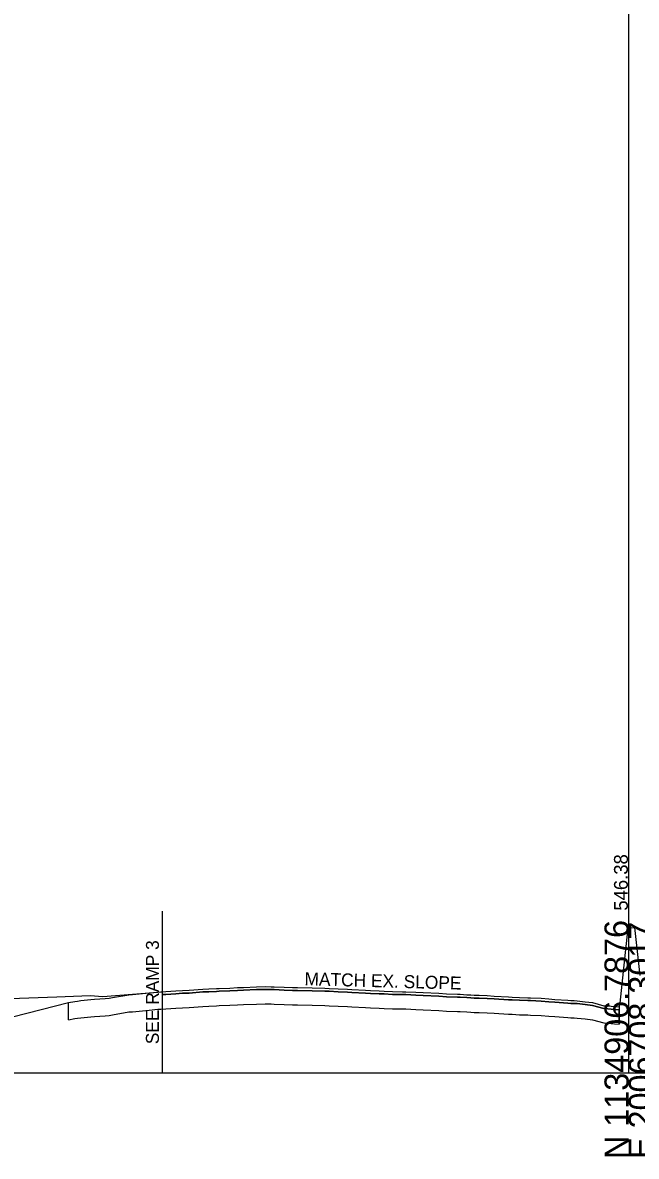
# Model space of a CAD drawing. Extents: x -201 to 2007062, y -213 to 1139737.
# Drawn here: x 1179.9 to 1250.9, y 990.3 to 1121.7 of the extents above; entities that cross this region are included whole.
import ezdxf

# ---------------------------------------------------------------- set-up
doc = ezdxf.new("R2010")
doc.units = 0
for name, color, linetype in [('RD_DTM_Design_FG', 7, 'Continuous'), ('RD_GPK_XS_Cell', 7, 'Continuous'), ('RD_XS_ExGround', 7, 'Continuous'), ('RD_XS_ExPaveRet', 7, 'Continuous'), ('RD_XS_PaveOvlay', 7, 'Continuous'), ('RD_XS_SideStreet', 7, 'Continuous'), ('RD_XS_TX_Elev_EX', 7, 'Continuous'), ('RD_XS_TX_Slope', 7, 'Continuous')]:
    doc.layers.add(name, color=color, linetype=linetype)

msp = doc.modelspace()

# ---------------------------------------------------------------- linework, layer by layer
at = {"layer": 'RD_DTM_Design_FG'}
msp.add_lwpolyline([(1069.88, 1075.08), (1095.05, 1049.89), (1143.64, 1001.26), (1148.38, 1002.83), (1161.65, 1007.23), (1162.29, 1007.33), (1165.65, 1007.87), (1166.43, 1007.93), (1171.66, 1008.34), (1172.95, 1008.39), (1183.82, 1008.8), (1187.67, 1008.95), (1189.12, 1008.83), (1196, 1009.37)], dxfattribs=at)
at = {"layer": 'RD_GPK_XS_Cell'}
for p, q in [((1250, 1000), (1250, 1250.21)), ((1000, 1000), (1250, 1000)), ((1250, 1000), (1500, 1000))]:
    msp.add_line(p, q, dxfattribs=at)
at = {"layer": 'RD_XS_ExGround'}
msp.add_lwpolyline([(1177.12, 1006.09), (1185.14, 1008.13), (1185.88, 1008.26), (1186.18, 1008.3), (1186.6, 1008.35), (1187.74, 1008.47), (1188.17, 1008.5), (1189.4, 1008.6), (1189.86, 1008.64), (1190.25, 1008.71), (1192.14, 1009.03), (1192.57, 1009.06), (1194.1, 1009.2), (1194.49, 1009.24), (1195.48, 1009.34), (1195.86, 1009.36), (1196.41, 1009.39), (1197.57, 1009.48), (1198.34, 1009.53), (1199.14, 1009.57), (1200.71, 1009.68), (1201.39, 1009.71), (1202.27, 1009.75), (1202.59, 1009.77), (1203.84, 1009.81), (1204.71, 1009.85), (1205.41, 1009.88), (1206.91, 1009.95), (1207.94, 1009.97), (1208.61, 1009.96), (1208.95, 1009.95), (1210.11, 1009.89), (1211.07, 1009.87), (1211.68, 1009.87), (1213.38, 1009.84), (1214.81, 1009.79), (1215.32, 1009.76), (1216.38, 1009.71), (1217.44, 1009.66), (1217.94, 1009.63), (1219.55, 1009.56), (1220.11, 1009.51), (1221.1, 1009.48), (1221.68, 1009.45), (1222.65, 1009.4), (1223.8, 1009.38), (1224.21, 1009.38), (1225.38, 1009.32), (1226.22, 1009.27), (1228.04, 1009.21), (1228.91, 1009.14), (1230.17, 1009.1), (1230.48, 1009.09), (1231.25, 1009.03), (1231.74, 1009.01), (1232.13, 1008.97), (1232.71, 1008.97), (1233.62, 1008.93), (1234.41, 1008.88), (1236.07, 1008.78), (1236.53, 1008.76), (1237.37, 1008.72), (1238.32, 1008.69), (1238.65, 1008.68), (1239.88, 1008.63), (1240.77, 1008.55), (1241.45, 1008.49), (1242.97, 1008.39), (1243.32, 1008.36), (1243.67, 1008.35), (1244.02, 1008.33), (1244.95, 1008.22), (1245.8, 1008.12), (1247.14, 1007.76), (1247.58, 1007.73), (1248.35, 1007.66), (1248.91, 1007.62), (1249.01, 1008.05), (1249.64, 1013.92), (1249.94, 1016.76), (1250.66, 1016.82), (1251.28, 1011.26)], dxfattribs=at)
at = {"layer": 'RD_XS_ExPaveRet'}
for p, q in [((1196, 1009.04), (1196, 1007.37)), ((1185.14, 1006.13), (1185.14, 1008.13)), ((1196.41, 1007.39), (1197.57, 1007.48)), ((1196.41, 1007.39), (1197.57, 1007.48)), ((1197.57, 1007.48), (1198.34, 1007.53)), ((1197.57, 1007.48), (1198.34, 1007.53)), ((1198.34, 1007.53), (1199.14, 1007.57)), ((1198.34, 1007.53), (1199.14, 1007.57)), ((1199.14, 1007.57), (1200.71, 1007.68)), ((1199.14, 1007.57), (1200.71, 1007.68)), ((1200.71, 1007.68), (1201.39, 1007.71)), ((1200.71, 1007.68), (1201.39, 1007.71)), ((1201.39, 1007.71), (1202.27, 1007.75)), ((1201.39, 1007.71), (1202.27, 1007.75)), ((1202.27, 1007.75), (1202.59, 1007.77)), ((1202.27, 1007.75), (1202.59, 1007.77)), ((1202.59, 1007.77), (1203.84, 1007.81)), ((1202.59, 1007.77), (1203.84, 1007.81)), ((1203.84, 1007.81), (1204.71, 1007.85)), ((1203.84, 1007.81), (1204.71, 1007.85)), ((1204.71, 1007.85), (1205.41, 1007.88)), ((1204.71, 1007.85), (1205.41, 1007.88)), ((1205.41, 1007.88), (1206.91, 1007.95)), ((1205.41, 1007.88), (1206.91, 1007.95)), ((1206.91, 1007.95), (1207.94, 1007.97)), ((1206.91, 1007.95), (1207.94, 1007.97)), ((1207.94, 1007.97), (1208.61, 1007.96)), ((1207.94, 1007.97), (1208.61, 1007.96)), ((1208.61, 1007.96), (1208.95, 1007.95)), ((1208.61, 1007.96), (1208.95, 1007.95)), ((1208.95, 1007.95), (1210.11, 1007.89)), ((1208.95, 1007.95), (1210.11, 1007.89)), ((1210.11, 1007.89), (1211.07, 1007.87)), ((1210.11, 1007.89), (1211.07, 1007.87)), ((1211.07, 1007.87), (1211.68, 1007.87)), ((1211.07, 1007.87), (1211.68, 1007.87)), ((1211.68, 1007.87), (1213.38, 1007.84)), ((1211.68, 1007.87), (1213.38, 1007.84)), ((1213.38, 1007.84), (1214.81, 1007.79)), ((1213.38, 1007.84), (1214.81, 1007.79)), ((1214.81, 1007.79), (1215.32, 1007.76)), ((1214.81, 1007.79), (1215.32, 1007.76)), ((1215.32, 1007.76), (1216.38, 1007.71)), ((1215.32, 1007.76), (1216.38, 1007.71)), ((1216.38, 1007.71), (1217.44, 1007.66)), ((1216.38, 1007.71), (1217.44, 1007.66)), ((1217.44, 1007.66), (1217.94, 1007.63)), ((1217.44, 1007.66), (1217.94, 1007.63)), ((1217.94, 1007.63), (1219.55, 1007.56)), ((1217.94, 1007.63), (1219.55, 1007.56)), ((1219.55, 1007.56), (1220.11, 1007.51)), ((1219.55, 1007.56), (1220.11, 1007.51)), ((1220.11, 1007.51), (1221.1, 1007.48)), ((1220.11, 1007.51), (1221.1, 1007.48)), ((1221.1, 1007.48), (1221.68, 1007.45)), ((1221.1, 1007.48), (1221.68, 1007.45)), ((1248.91, 1007.62), (1248.91, 1005.62)), ((1185.14, 1006.13), (1185.88, 1006.26)), ((1185.88, 1006.26), (1186.18, 1006.3)), ((1186.18, 1006.3), (1186.6, 1006.35)), ((1186.6, 1006.35), (1187.74, 1006.47)), ((1187.74, 1006.47), (1188.17, 1006.5)), ((1188.17, 1006.5), (1189.4, 1006.6)), ((1189.4, 1006.6), (1189.86, 1006.64)), ((1189.86, 1006.64), (1190.25, 1006.71)), ((1190.25, 1006.71), (1192.14, 1007.03)), ((1192.14, 1007.03), (1192.57, 1007.06)), ((1192.57, 1007.06), (1194.1, 1007.2)), ((1194.1, 1007.2), (1194.49, 1007.24)), ((1194.49, 1007.24), (1195.48, 1007.34)), ((1195.48, 1007.34), (1195.86, 1007.36)), ((1195.86, 1007.36), (1196.41, 1007.39)), ((1196, 1007.37), (1196.41, 1007.39)), ((1221.68, 1007.45), (1222.65, 1007.4)), ((1221.68, 1007.45), (1222.65, 1007.4)), ((1222.65, 1007.4), (1223.8, 1007.38)), ((1222.65, 1007.4), (1223.8, 1007.38)), ((1223.8, 1007.38), (1224.21, 1007.38)), ((1223.8, 1007.38), (1224.21, 1007.38)), ((1224.21, 1007.38), (1225.38, 1007.32)), ((1224.21, 1007.38), (1225.38, 1007.32)), ((1225.38, 1007.32), (1226.22, 1007.27)), ((1225.38, 1007.32), (1226.22, 1007.27)), ((1226.22, 1007.27), (1228.04, 1007.21)), ((1226.22, 1007.27), (1228.04, 1007.21)), ((1228.04, 1007.21), (1228.91, 1007.14)), ((1228.04, 1007.21), (1228.91, 1007.14)), ((1228.91, 1007.14), (1230.17, 1007.1)), ((1228.91, 1007.14), (1230.17, 1007.1)), ((1230.17, 1007.1), (1230.48, 1007.09)), ((1230.17, 1007.1), (1230.48, 1007.09)), ((1230.48, 1007.09), (1231.25, 1007.03)), ((1230.48, 1007.09), (1231.25, 1007.03)), ((1231.25, 1007.03), (1231.74, 1007.01)), ((1231.25, 1007.03), (1231.74, 1007.01)), ((1231.74, 1007.01), (1232.13, 1006.97)), ((1231.74, 1007.01), (1232.13, 1006.97)), ((1232.13, 1006.97), (1232.71, 1006.97)), ((1232.13, 1006.97), (1232.71, 1006.97)), ((1232.71, 1006.97), (1233.62, 1006.93)), ((1232.71, 1006.97), (1233.62, 1006.93)), ((1233.62, 1006.93), (1234.41, 1006.88)), ((1233.62, 1006.93), (1234.41, 1006.88)), ((1234.41, 1006.88), (1236.07, 1006.78)), ((1234.41, 1006.88), (1236.07, 1006.78)), ((1236.07, 1006.78), (1236.53, 1006.76)), ((1236.07, 1006.78), (1236.53, 1006.76)), ((1236.53, 1006.76), (1237.37, 1006.72)), ((1236.53, 1006.76), (1237.37, 1006.72)), ((1237.37, 1006.72), (1238.32, 1006.69)), ((1237.37, 1006.72), (1238.32, 1006.69)), ((1238.32, 1006.69), (1238.65, 1006.68)), ((1238.32, 1006.69), (1238.65, 1006.68)), ((1238.65, 1006.68), (1239.88, 1006.63)), ((1238.65, 1006.68), (1239.88, 1006.63)), ((1239.88, 1006.63), (1240.77, 1006.55)), ((1239.88, 1006.63), (1240.77, 1006.55)), ((1240.77, 1006.55), (1241.45, 1006.49)), ((1240.77, 1006.55), (1241.45, 1006.49)), ((1241.45, 1006.49), (1242.97, 1006.39)), ((1241.45, 1006.49), (1242.97, 1006.39)), ((1242.97, 1006.39), (1243.32, 1006.36)), ((1242.97, 1006.39), (1243.32, 1006.36)), ((1243.32, 1006.36), (1243.67, 1006.35)), ((1243.32, 1006.36), (1243.67, 1006.35)), ((1243.67, 1006.35), (1244.02, 1006.33)), ((1243.67, 1006.35), (1244.02, 1006.33)), ((1244.02, 1006.33), (1244.95, 1006.22)), ((1244.02, 1006.33), (1244.95, 1006.22)), ((1244.95, 1006.22), (1245.8, 1006.12)), ((1244.95, 1006.22), (1245.8, 1006.12)), ((1248.91, 1005.62), (1248.91, 1007.29)), ((1245.8, 1006.12), (1247.14, 1005.76)), ((1245.8, 1006.12), (1247.14, 1005.76)), ((1247.14, 1005.76), (1247.58, 1005.73)), ((1247.14, 1005.76), (1247.58, 1005.73)), ((1247.58, 1005.73), (1248.35, 1005.66)), ((1247.58, 1005.73), (1248.35, 1005.66)), ((1248.35, 1005.66), (1248.91, 1005.62)), ((1248.35, 1005.66), (1248.91, 1005.62))]:
    msp.add_line(p, q, dxfattribs=at)
msp.add_lwpolyline([(1248.91, 1007.29), (1248.35, 1007.33), (1247.58, 1007.4), (1247.14, 1007.42), (1245.8, 1007.79), (1244.95, 1007.89), (1244.02, 1008), (1243.67, 1008.02), (1243.32, 1008.03), (1242.97, 1008.05), (1241.45, 1008.15), (1240.77, 1008.22), (1239.88, 1008.3), (1238.65, 1008.35), (1238.32, 1008.36), (1237.37, 1008.39), (1236.53, 1008.43), (1236.07, 1008.45), (1234.41, 1008.55), (1233.62, 1008.59), (1232.71, 1008.63), (1232.13, 1008.64), (1231.74, 1008.68), (1231.25, 1008.7), (1230.48, 1008.75), (1230.17, 1008.76), (1228.91, 1008.8), (1228.04, 1008.88), (1226.22, 1008.94), (1225.38, 1008.98), (1224.21, 1009.04), (1223.8, 1009.04), (1222.65, 1009.07), (1221.68, 1009.12), (1221.1, 1009.15), (1220.11, 1009.18), (1219.55, 1009.22), (1217.94, 1009.3), (1217.44, 1009.33), (1216.38, 1009.38), (1215.32, 1009.43), (1214.81, 1009.46), (1213.38, 1009.5), (1211.68, 1009.54), (1211.07, 1009.54), (1210.11, 1009.56), (1208.95, 1009.62), (1208.61, 1009.63), (1207.94, 1009.63), (1206.91, 1009.62), (1205.41, 1009.55), (1204.71, 1009.51), (1203.84, 1009.48), (1202.59, 1009.44), (1202.27, 1009.42), (1201.39, 1009.38), (1200.71, 1009.35), (1199.14, 1009.23), (1198.34, 1009.2), (1197.57, 1009.15), (1196.41, 1009.06), (1196, 1009.04)], dxfattribs=at)
at = {"layer": 'RD_XS_PaveOvlay'}
msp.add_line((1196, 1009.37), (1196, 1009.04), dxfattribs=at)
for points in [[(1196, 1009.37), (1196.41, 1009.39), (1197.57, 1009.48), (1198.34, 1009.53), (1199.14, 1009.57), (1200.71, 1009.68), (1201.39, 1009.71), (1202.27, 1009.75), (1202.59, 1009.77), (1203.84, 1009.81), (1204.71, 1009.85), (1205.41, 1009.88), (1206.91, 1009.95), (1207.94, 1009.97), (1208.61, 1009.96), (1208.95, 1009.95), (1210.11, 1009.89), (1211.07, 1009.87), (1211.68, 1009.87), (1213.38, 1009.84), (1214.81, 1009.79), (1215.32, 1009.76), (1216.38, 1009.71), (1217.44, 1009.66), (1217.94, 1009.63), (1219.55, 1009.56), (1220.11, 1009.51), (1221.1, 1009.48), (1221.68, 1009.45), (1222.65, 1009.4), (1223.8, 1009.38), (1224.21, 1009.38), (1225.38, 1009.32), (1226.22, 1009.27), (1228.04, 1009.21), (1228.91, 1009.14), (1230.17, 1009.1), (1230.48, 1009.09), (1231.25, 1009.03), (1231.74, 1009.01), (1232.13, 1008.97), (1232.71, 1008.97), (1233.62, 1008.93), (1234.41, 1008.88), (1236.07, 1008.78), (1236.53, 1008.76), (1237.37, 1008.72), (1238.32, 1008.69), (1238.65, 1008.68), (1239.88, 1008.63), (1240.77, 1008.55), (1241.45, 1008.49), (1242.97, 1008.39), (1243.32, 1008.36), (1243.67, 1008.35), (1244.02, 1008.33), (1244.95, 1008.22), (1245.8, 1008.12), (1247.14, 1007.76), (1247.58, 1007.73), (1248.35, 1007.66), (1248.91, 1007.62), (1248.91, 1007.62)], [(1196, 1009.04), (1196.41, 1009.06), (1197.57, 1009.15), (1198.34, 1009.2), (1199.14, 1009.23), (1200.71, 1009.35), (1201.39, 1009.38), (1202.27, 1009.42), (1202.59, 1009.44), (1203.84, 1009.48), (1204.71, 1009.51), (1205.41, 1009.55), (1206.91, 1009.62), (1207.94, 1009.63), (1208.61, 1009.63), (1208.95, 1009.62), (1210.11, 1009.56), (1211.07, 1009.54), (1211.68, 1009.54), (1213.38, 1009.5), (1214.81, 1009.46), (1215.32, 1009.43), (1216.38, 1009.38), (1217.44, 1009.33), (1217.94, 1009.3), (1219.55, 1009.22), (1220.11, 1009.18), (1221.1, 1009.15), (1221.68, 1009.12), (1222.65, 1009.07), (1223.8, 1009.04), (1224.21, 1009.04), (1225.38, 1008.98), (1226.22, 1008.94), (1228.04, 1008.88), (1228.91, 1008.8), (1230.17, 1008.76), (1230.48, 1008.75), (1231.25, 1008.7), (1231.74, 1008.68), (1232.13, 1008.64), (1232.71, 1008.63), (1233.62, 1008.59), (1234.41, 1008.55), (1236.07, 1008.45), (1236.53, 1008.43), (1237.37, 1008.39), (1238.32, 1008.36), (1238.65, 1008.35), (1239.88, 1008.3), (1240.77, 1008.22), (1241.45, 1008.15), (1242.97, 1008.05), (1243.32, 1008.03), (1243.67, 1008.02), (1244.02, 1008), (1244.95, 1007.89), (1245.8, 1007.79), (1247.14, 1007.42), (1247.58, 1007.4), (1248.35, 1007.33), (1248.91, 1007.29), (1248.91, 1007.29)]]:
    msp.add_lwpolyline(points, dxfattribs=at)
at = {"layer": 'RD_XS_SideStreet'}
msp.add_line((1196, 1018.71), (1196, 1000.03), dxfattribs=at)

# ---------------------------------------------------------------- texts
at = {"layer": 'RD_GPK_XS_Cell'}
for s, p in [('N 1134906.7876', (1250, 990)), ('E 2006708.3017', (1252.8, 990))]:
    msp.add_text(s, height=2.8, rotation=90, dxfattribs=at).set_placement(p)
at = {"layer": 'RD_XS_SideStreet'}
msp.add_text('SEE RAMP 3', height=1.5, rotation=90, dxfattribs=at).set_placement((1195.62, 1003.3))
at = {"layer": 'RD_XS_TX_Elev_EX'}
msp.add_text('546.38', height=1.6, rotation=90, dxfattribs=at).set_placement((1249.9, 1018.77))
at = {"layer": 'RD_XS_TX_Slope'}
msp.add_text('MATCH EX. SLOPE', height=1.5, rotation=358.3671, dxfattribs=at).set_placement((1212.46, 1010.14))

doc.saveas('drawing.dxf')
